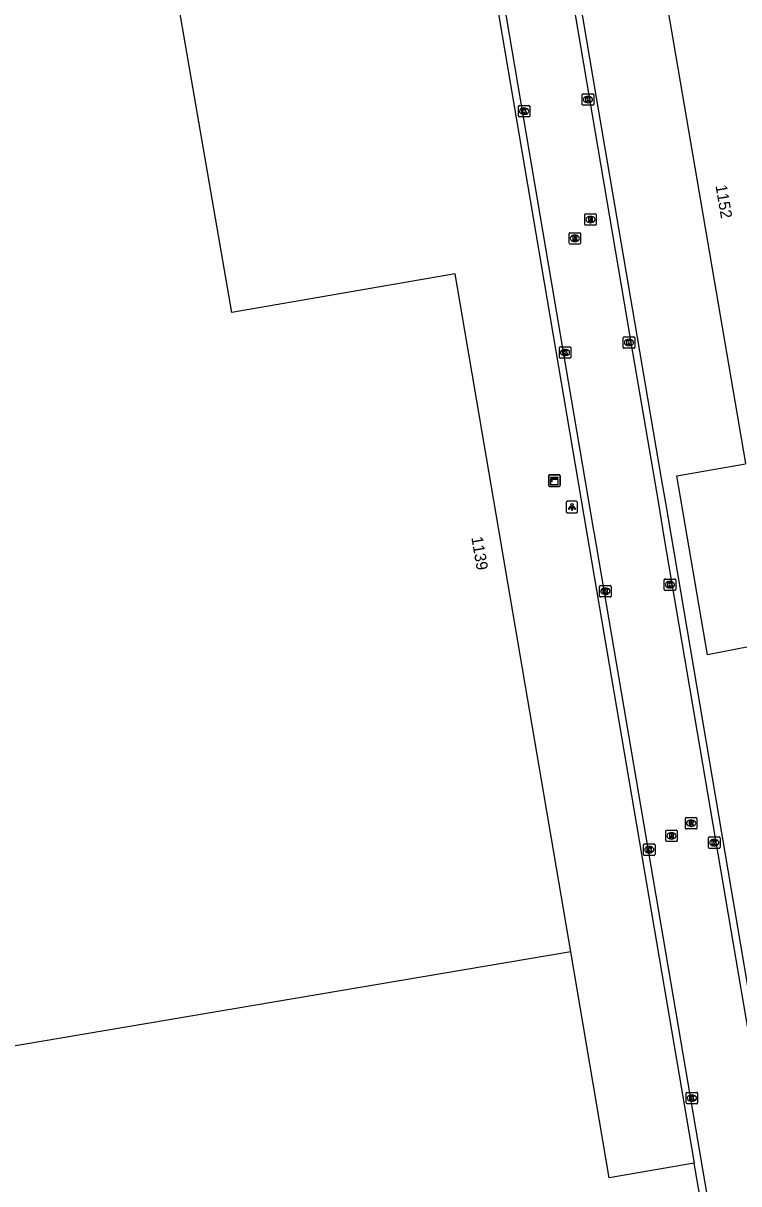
# Model space of a CAD drawing. Extents: x 154324 to 155743, y 382939 to 384183.
# Drawn here: x 154819.6 to 154882.3, y 383668.1 to 383769.7 of the extents above; entities that cross this region are included whole.
import ezdxf

# ---------------------------------------------------------------- set-up
doc = ezdxf.new("R2010")
doc.units = 0
for name, color, linetype in [('IMGEO_Kast', 7, 'Continuous'), ('IMGEO_Kolk', 7, 'Continuous'), ('IMGEO_Lichtpunt', 7, 'Continuous'), ('IMGEO_Pand', 7, 'Continuous'), ('IMGEO_Pand_nummerreeks', 7, 'Continuous'), ('IMGEO_Parkeervlak_open', 7, 'Continuous'), ('IMGEO_Rijbaan_lokaal_gesloten', 7, 'Continuous'), ('IMGEO_Rijbaan_lokaal_open', 7, 'Continuous'), ('IMGEO_Rioolput', 7, 'Continuous'), ('IMGEO_Voetpad_open', 7, 'Continuous')]:
    doc.layers.add(name, color=color, linetype=linetype)

msp = doc.modelspace()

# ---------------------------------------------------------------- linework, layer by layer
at = {"layer": 'IMGEO_Kast'}
for p, q in [((154865.64, 383729.2), (154865.64, 383730.04)), ((154865.64, 383730.04), (154865.64, 383729.2)), ((154865.71, 383730.12), (154866.55, 383730.12)), ((154866.55, 383730.12), (154865.71, 383730.12)), ((154866.64, 383730.05), (154866.64, 383729.21)), ((154866.64, 383729.21), (154866.64, 383730.05)), ((154866.56, 383729.12), (154865.72, 383729.12)), ((154865.72, 383729.12), (154866.56, 383729.12))]:
    msp.add_line(p, q, dxfattribs=at)
for points in [[(154865.83, 383729.91), (154866.43, 383729.91), (154866.43, 383729.83), (154865.83, 383729.83), (154865.83, 383729.91)], [(154865.83, 383729.74), (154866.43, 383729.74), (154866.43, 383729.25), (154865.83, 383729.25), (154865.83, 383729.74)]]:
    msp.add_lwpolyline(points, dxfattribs=at)
msp.add_circle((154865.91, 383729.59), 0.0377, dxfattribs=at)
for centre, start, end in [((154865.71, 383730.05), 92.4484, 184.2845), ((154865.71, 383730.05), 92.4484, 184.2845), ((154866.56, 383730.05), 2.4484, 94.2845), ((154866.56, 383730.05), 2.4484, 94.2845), ((154865.71, 383729.2), 182.4484, 274.2845), ((154865.71, 383729.2), 182.4484, 274.2845), ((154866.56, 383729.2), 272.4484, 4.2845), ((154866.56, 383729.2), 272.4484, 4.2845)]:
    msp.add_arc(centre, 0.0779, start, end, dxfattribs=at)
at = {"layer": 'IMGEO_Kolk'}
for p, q in [((154868.58, 383762.55), (154868.58, 383763.4)), ((154868.65, 383763.48), (154869.5, 383763.48)), ((154869.06, 383763.25), (154869.09, 383763.25)), ((154869.58, 383763.4), (154869.58, 383762.55)), ((154862.98, 383761.52), (154862.98, 383762.38)), ((154863.06, 383762.45), (154863.91, 383762.45)), ((154863.47, 383762.23), (154863.5, 383762.23)), ((154863.99, 383762.38), (154863.99, 383761.52)), ((154869.5, 383762.47), (154868.65, 383762.47)), ((154869.09, 383762.7), (154869.06, 383762.7)), ((154863.91, 383761.45), (154863.06, 383761.45)), ((154863.49, 383761.67), (154863.47, 383761.67)), ((154872.16, 383741.28), (154872.16, 383742.13)), ((154872.24, 383742.21), (154873.09, 383742.21)), ((154872.65, 383741.99), (154872.68, 383741.99)), ((154873.17, 383742.13), (154873.17, 383741.28)), ((154866.57, 383740.4), (154866.57, 383741.26)), ((154866.64, 383741.33), (154867.5, 383741.33)), ((154867.06, 383741.11), (154867.08, 383741.11)), ((154867.57, 383741.26), (154867.57, 383740.4)), ((154873.09, 383741.21), (154872.24, 383741.21)), ((154872.67, 383741.43), (154872.65, 383741.43)), ((154867.5, 383740.33), (154866.64, 383740.33)), ((154867.08, 383740.55), (154867.06, 383740.55)), ((154875.76, 383720.09), (154875.76, 383720.94)), ((154875.83, 383721.01), (154876.68, 383721.01)), ((154876.24, 383720.79), (154876.27, 383720.79)), ((154876.76, 383720.94), (154876.76, 383720.09)), ((154870.1, 383719.51), (154870.1, 383720.36)), ((154870.17, 383720.44), (154871.03, 383720.44)), ((154870.61, 383719.66), (154870.58, 383719.66)), ((154870.59, 383720.22), (154870.61, 383720.22)), ((154871.1, 383720.36), (154871.1, 383719.51)), ((154876.68, 383720.01), (154875.83, 383720.01)), ((154876.27, 383720.23), (154876.24, 383720.23)), ((154871.03, 383719.44), (154870.17, 383719.44)), ((154879.64, 383697.52), (154879.64, 383698.37)), ((154879.71, 383698.45), (154880.56, 383698.45)), ((154880.12, 383698.22), (154880.15, 383698.22)), ((154880.64, 383698.37), (154880.64, 383697.52)), ((154873.95, 383696.89), (154873.95, 383697.74)), ((154874.02, 383697.82), (154874.87, 383697.82)), ((154874.43, 383697.6), (154874.46, 383697.6)), ((154874.95, 383697.74), (154874.95, 383696.89)), ((154880.56, 383697.44), (154879.71, 383697.44)), ((154880.15, 383697.67), (154880.12, 383697.67)), ((154874.87, 383696.82), (154874.02, 383696.82)), ((154874.46, 383697.04), (154874.43, 383697.04)), ((154877.68, 383675.16), (154877.68, 383676.01)), ((154877.75, 383676.08), (154878.6, 383676.08)), ((154878.16, 383675.86), (154878.19, 383675.86)), ((154878.68, 383676.01), (154878.68, 383675.16)), ((154878.6, 383675.08), (154877.75, 383675.08)), ((154878.19, 383675.3), (154878.16, 383675.3))]:
    msp.add_line(p, q, dxfattribs=at)
for points in [[(154868.58, 383762.55), (154868.58, 383763.4)], [(154868.65, 383763.48), (154869.5, 383763.48)], [(154868.9, 383763.17), (154869.02, 383763.17), (154869.02, 383763.02), (154869.15, 383763.17), (154869.31, 383763.17), (154869.17, 383763.02), (154869.32, 383762.77), (154869.17, 383762.77), (154869.08, 383762.94), (154869.02, 383762.87), (154869.02, 383762.77), (154868.9, 383762.77), (154868.9, 383763.17)], [(154869.58, 383763.4), (154869.58, 383762.55)], [(154862.98, 383761.52), (154862.98, 383762.38)], [(154863.06, 383762.45), (154863.91, 383762.45)], [(154863.3, 383762.15), (154863.43, 383762.15), (154863.43, 383762), (154863.56, 383762.15), (154863.72, 383762.15), (154863.58, 383762), (154863.73, 383761.75), (154863.58, 383761.75), (154863.49, 383761.91), (154863.43, 383761.85), (154863.43, 383761.75), (154863.3, 383761.75), (154863.3, 383762.15)], [(154863.99, 383762.38), (154863.99, 383761.52)], [(154869.5, 383762.47), (154868.65, 383762.47)], [(154863.91, 383761.45), (154863.06, 383761.45)], [(154872.16, 383741.28), (154872.16, 383742.13)], [(154872.24, 383742.21), (154873.09, 383742.21)], [(154872.48, 383741.91), (154872.61, 383741.91), (154872.61, 383741.76), (154872.74, 383741.91), (154872.9, 383741.91), (154872.76, 383741.76), (154872.91, 383741.51), (154872.76, 383741.51), (154872.67, 383741.67), (154872.61, 383741.6), (154872.61, 383741.51), (154872.48, 383741.51), (154872.48, 383741.91)], [(154873.17, 383742.13), (154873.17, 383741.28)], [(154866.57, 383740.4), (154866.57, 383741.26)], [(154866.64, 383741.33), (154867.5, 383741.33)], [(154866.89, 383741.03), (154867.01, 383741.03), (154867.01, 383740.88), (154867.14, 383741.03), (154867.31, 383741.03), (154867.16, 383740.88), (154867.31, 383740.63), (154867.16, 383740.63), (154867.08, 383740.8), (154867.01, 383740.73), (154867.01, 383740.63), (154866.89, 383740.63), (154866.89, 383741.03)], [(154867.57, 383741.26), (154867.57, 383740.4)], [(154873.09, 383741.21), (154872.24, 383741.21)], [(154867.5, 383740.33), (154866.64, 383740.33)], [(154875.76, 383720.09), (154875.76, 383720.94)], [(154875.83, 383721.01), (154876.68, 383721.01)], [(154876.08, 383720.71), (154876.2, 383720.71), (154876.2, 383720.56), (154876.33, 383720.71), (154876.49, 383720.71), (154876.35, 383720.56), (154876.5, 383720.31), (154876.35, 383720.31), (154876.26, 383720.48), (154876.2, 383720.41), (154876.2, 383720.31), (154876.08, 383720.31), (154876.08, 383720.71)], [(154876.76, 383720.94), (154876.76, 383720.09)], [(154870.1, 383719.51), (154870.1, 383720.36)], [(154870.17, 383720.44), (154871.03, 383720.44)], [(154870.42, 383720.14), (154870.54, 383720.14), (154870.54, 383719.99), (154870.67, 383720.14), (154870.84, 383720.14), (154870.69, 383719.99), (154870.84, 383719.74), (154870.69, 383719.74), (154870.61, 383719.9), (154870.54, 383719.84), (154870.54, 383719.74), (154870.42, 383719.74), (154870.42, 383720.14)], [(154871.1, 383720.36), (154871.1, 383719.51)], [(154876.68, 383720.01), (154875.83, 383720.01)], [(154871.03, 383719.44), (154870.17, 383719.44)], [(154879.64, 383697.52), (154879.64, 383698.37)], [(154879.71, 383698.45), (154880.56, 383698.45)], [(154879.96, 383698.14), (154880.08, 383698.14), (154880.08, 383697.99), (154880.21, 383698.14), (154880.37, 383698.14), (154880.23, 383697.99), (154880.38, 383697.74), (154880.23, 383697.74), (154880.14, 383697.91), (154880.08, 383697.84), (154880.08, 383697.74), (154879.96, 383697.74), (154879.96, 383698.14)], [(154880.64, 383698.37), (154880.64, 383697.52)], [(154873.95, 383696.89), (154873.95, 383697.74)], [(154874.02, 383697.82), (154874.87, 383697.82)], [(154874.27, 383697.52), (154874.39, 383697.52), (154874.39, 383697.37), (154874.52, 383697.52), (154874.68, 383697.52), (154874.54, 383697.37), (154874.69, 383697.12), (154874.54, 383697.12), (154874.45, 383697.28), (154874.39, 383697.22), (154874.39, 383697.12), (154874.27, 383697.12), (154874.27, 383697.52)], [(154874.95, 383697.74), (154874.95, 383696.89)], [(154880.56, 383697.44), (154879.71, 383697.44)], [(154874.87, 383696.82), (154874.02, 383696.82)], [(154877.68, 383675.16), (154877.68, 383676.01)], [(154877.75, 383676.08), (154878.6, 383676.08)], [(154878, 383675.78), (154878.12, 383675.78), (154878.12, 383675.63), (154878.25, 383675.78), (154878.41, 383675.78), (154878.27, 383675.63), (154878.42, 383675.38), (154878.27, 383675.38), (154878.18, 383675.55), (154878.12, 383675.48), (154878.12, 383675.38), (154878, 383675.38), (154878, 383675.78)], [(154878.68, 383676.01), (154878.68, 383675.16)], [(154878.6, 383675.08), (154877.75, 383675.08)]]:
    msp.add_lwpolyline(points, dxfattribs=at)
for centre, start, end in [((154868.65, 383763.4), 91.552, 178.448), ((154868.65, 383763.4), 91.552, 178.448), ((154869.5, 383763.4), 1.552, 88.448), ((154869.5, 383763.4), 1.552, 88.448), ((154863.06, 383762.37), 91.552, 178.448), ((154863.06, 383762.37), 91.552, 178.448), ((154863.91, 383762.37), 1.552, 88.448), ((154863.91, 383762.37), 1.552, 88.448), ((154868.65, 383762.55), 181.552, 268.448), ((154868.65, 383762.55), 181.552, 268.448), ((154869.5, 383762.55), 271.552, 358.448), ((154869.5, 383762.55), 271.552, 358.448), ((154863.06, 383761.53), 181.552, 268.448), ((154863.06, 383761.53), 181.552, 268.448), ((154863.91, 383761.53), 271.552, 358.448), ((154863.91, 383761.53), 271.552, 358.448), ((154872.24, 383742.13), 91.552, 178.448), ((154872.24, 383742.13), 91.552, 178.448), ((154873.09, 383742.13), 1.552, 88.448), ((154873.09, 383742.13), 1.552, 88.448), ((154866.65, 383741.26), 91.552, 178.448), ((154866.65, 383741.26), 91.552, 178.448), ((154867.49, 383741.26), 1.552, 88.448), ((154867.49, 383741.26), 1.552, 88.448), ((154872.24, 383741.28), 181.552, 268.448), ((154872.24, 383741.28), 181.552, 268.448), ((154873.09, 383741.28), 271.552, 358.448), ((154873.09, 383741.28), 271.552, 358.448), ((154866.65, 383740.41), 181.552, 268.448), ((154866.65, 383740.41), 181.552, 268.448), ((154867.49, 383740.41), 271.552, 358.448), ((154867.49, 383740.41), 271.552, 358.448), ((154875.83, 383720.94), 91.552, 178.448), ((154875.83, 383720.94), 91.552, 178.448), ((154876.68, 383720.94), 1.552, 88.448), ((154876.68, 383720.94), 1.552, 88.448), ((154870.17, 383720.36), 91.552, 178.448), ((154870.17, 383720.36), 91.552, 178.448), ((154870.17, 383719.51), 181.552, 268.448), ((154870.17, 383719.51), 181.552, 268.448), ((154871.02, 383720.36), 1.552, 88.448), ((154871.02, 383720.36), 1.552, 88.448), ((154871.02, 383719.51), 271.552, 358.448), ((154871.02, 383719.51), 271.552, 358.448), ((154875.83, 383720.09), 181.552, 268.448), ((154875.83, 383720.09), 181.552, 268.448), ((154876.68, 383720.09), 271.552, 358.448), ((154876.68, 383720.09), 271.552, 358.448), ((154879.71, 383698.37), 91.552, 178.448), ((154879.71, 383698.37), 91.552, 178.448), ((154880.56, 383698.37), 1.552, 88.448), ((154880.56, 383698.37), 1.552, 88.448), ((154874.02, 383697.74), 91.552, 178.448), ((154874.02, 383697.74), 91.552, 178.448), ((154874.87, 383697.74), 1.552, 88.448), ((154874.87, 383697.74), 1.552, 88.448), ((154879.71, 383697.52), 181.552, 268.448), ((154879.71, 383697.52), 181.552, 268.448), ((154880.56, 383697.52), 271.552, 358.448), ((154880.56, 383697.52), 271.552, 358.448), ((154874.02, 383696.89), 181.552, 268.448), ((154874.02, 383696.89), 181.552, 268.448), ((154874.87, 383696.89), 271.552, 358.448), ((154874.87, 383696.89), 271.552, 358.448), ((154877.75, 383676.01), 91.552, 178.448), ((154877.75, 383676.01), 91.552, 178.448), ((154878.6, 383676.01), 1.552, 88.448), ((154878.6, 383676.01), 1.552, 88.448), ((154877.75, 383675.16), 181.552, 268.448), ((154877.75, 383675.16), 181.552, 268.448), ((154878.6, 383675.16), 271.552, 358.448), ((154878.6, 383675.16), 271.552, 358.448)]:
    msp.add_arc(centre, 0.0765, start, end, dxfattribs=at)
for centre, major_axis, ratio, start_param, end_param in [((154869.06, 383762.97), (-0.387, 0.002), 0.722429, 4.712389, 7.853982), ((154869.09, 383762.97), (-0.39, 0.002), 0.717154, 1.570796, 4.712389), ((154863.47, 383761.95), (-0.387, 0.002), 0.722429, 4.712389, 7.853982), ((154863.5, 383761.95), (-0.39, 0.002), 0.717154, 1.570796, 4.712389), ((154872.65, 383741.71), (-0.387, 0.002), 0.722429, 4.712389, 7.853982), ((154872.68, 383741.71), (-0.39, 0.002), 0.717154, 1.570796, 4.712389), ((154867.06, 383740.83), (-0.387, 0.002), 0.722429, 4.712389, 7.853982), ((154867.08, 383740.83), (-0.39, 0.002), 0.717154, 1.570796, 4.712389), ((154876.24, 383720.51), (-0.387, 0.002), 0.722429, 4.712389, 7.853982), ((154876.27, 383720.51), (-0.39, 0.002), 0.717154, 1.570796, 4.712389), ((154870.59, 383719.94), (-0.387, 0.002), 0.722429, 4.712389, 7.853982), ((154870.61, 383719.94), (-0.39, 0.002), 0.717154, 1.570796, 4.712389), ((154880.12, 383697.94), (-0.387, 0.002), 0.722429, 4.712389, 7.853982), ((154880.15, 383697.94), (-0.39, 0.002), 0.717154, 1.570796, 4.712389), ((154874.43, 383697.32), (-0.387, 0.002), 0.722429, 4.712389, 7.853982), ((154874.46, 383697.32), (-0.39, 0.002), 0.717154, 1.570796, 4.712389), ((154878.16, 383675.58), (-0.387, 0.002), 0.722429, 4.712389, 7.853982), ((154878.19, 383675.58), (-0.39, 0.002), 0.717154, 1.570796, 4.712389)]:
    msp.add_ellipse(centre, major_axis=major_axis, ratio=ratio, start_param=start_param, end_param=end_param, dxfattribs=at)
at = {"layer": 'IMGEO_Lichtpunt'}
for p, q in [((154867.17, 383727.71), (154867.17, 383726.91)), ((154867.17, 383727.71), (154867.17, 383726.91)), ((154868.07, 383727.81), (154867.26, 383727.81)), ((154868.07, 383727.81), (154867.26, 383727.81)), ((154868.17, 383726.91), (154868.17, 383727.71)), ((154868.17, 383726.91), (154868.17, 383727.71)), ((154867.26, 383726.81), (154868.07, 383726.81)), ((154867.26, 383726.81), (154868.07, 383726.81))]:
    msp.add_line(p, q, dxfattribs=at)
for points in [[(154867.54, 383727.38), (154867.58, 383727.35), (154867.4, 383727.09), (154867.36, 383727.12), (154867.54, 383727.38)], [(154867.65, 383727.33), (154867.69, 383727.33), (154867.69, 383727.01), (154867.65, 383727.01), (154867.65, 383727.33)], [(154867.76, 383727.35), (154867.79, 383727.38), (154867.98, 383727.11), (154867.94, 383727.09), (154867.76, 383727.35)]]:
    msp.add_lwpolyline(points, dxfattribs=at)
msp.add_circle((154867.67, 383727.51), 0.0994, dxfattribs=at)
for centre, start, end in [((154867.26, 383727.71), 90, 180), ((154867.26, 383727.71), 90, 180), ((154868.07, 383727.71), 0, 90), ((154868.07, 383727.71), 0, 90), ((154867.26, 383726.91), 180, 270), ((154867.26, 383726.91), 180, 270), ((154868.07, 383726.91), 270, 0), ((154868.07, 383726.91), 270, 360)]:
    msp.add_arc(centre, 0.0946, start, end, dxfattribs=at)
at = {"layer": 'IMGEO_Pand'}
for points in [[(154867.57, 383688.39), (154857.46, 383747.73), (154837.88, 383744.34), (154832.77, 383773.85), (154852.43, 383777.26), (154848.68, 383799.11), (154846.65, 383810.94)], [(154875.11, 383776.48), (154882.87, 383731.11)], [(154867.57, 383688.39), (154787.88, 383674.89)]]:
    msp.add_lwpolyline(points, dxfattribs=at)
at = {"layer": 'IMGEO_Parkeervlak_open'}
msp.add_lwpolyline([(154878.39, 383669.9), (154870.94, 383668.6), (154867.57, 383688.39)], dxfattribs=at)
at = {"layer": 'IMGEO_Rijbaan_lokaal_gesloten'}
for points in [[(154859.21, 383821.78), (154860.59, 383813.67), (154872.99, 383740.87), (154875.26, 383727.61), (154875.73, 383724.69), (154937.89, 383359.92)], [(154854.43, 383814.31), (154854.65, 383812.99), (154854.81, 383812.02), (154858.48, 383790.5), (154869.56, 383725.26), (154869.6, 383725.13), (154932.04, 383358.96)]]:
    msp.add_lwpolyline(points, dxfattribs=at)
at = {"layer": 'IMGEO_Rijbaan_lokaal_open'}
for points in [[(154853.94, 383813.59), (154856.18, 383800.4), (154857.87, 383790.41), (154868.95, 383725.16), (154878.39, 383669.9)], [(154867.75, 383775.23), (154869.8, 383763.15), (154873.59, 383740.95), (154875.5, 383729.82), (154875.86, 383727.69), (154876.35, 383724.76), (154883, 383685.74), (154886, 383668.1)], [(154880.3, 383658.76), (154878.39, 383669.9)]]:
    msp.add_lwpolyline(points, dxfattribs=at)
at = {"layer": 'IMGEO_Rioolput'}
for p, q in [((154868.87, 383752.97), (154869.72, 383752.97)), ((154868.8, 383752.05), (154868.8, 383752.9)), ((154869.72, 383751.97), (154868.87, 383751.97)), ((154869.28, 383752.75), (154869.31, 383752.75)), ((154869.31, 383752.19), (154869.28, 383752.19)), ((154869.8, 383752.9), (154869.8, 383752.05)), ((154867.43, 383750.39), (154867.43, 383751.24)), ((154867.5, 383751.32), (154868.35, 383751.32)), ((154867.91, 383751.1), (154867.94, 383751.1)), ((154868.43, 383751.24), (154868.43, 383750.39)), ((154868.35, 383750.32), (154867.5, 383750.32)), ((154867.94, 383750.54), (154867.91, 383750.54)), ((154877.61, 383699.21), (154877.61, 383700.06)), ((154877.68, 383700.14), (154878.53, 383700.14)), ((154878.12, 383699.36), (154878.09, 383699.36)), ((154878.1, 383699.92), (154878.12, 383699.92)), ((154878.61, 383700.06), (154878.61, 383699.21)), ((154875.89, 383698.11), (154875.89, 383698.96)), ((154875.97, 383699.03), (154876.82, 383699.03)), ((154876.38, 383698.81), (154876.4, 383698.81)), ((154876.4, 383698.25), (154876.38, 383698.25)), ((154876.89, 383698.96), (154876.89, 383698.11)), ((154878.53, 383699.14), (154877.68, 383699.14)), ((154876.82, 383698.03), (154875.97, 383698.03))]:
    msp.add_line(p, q, dxfattribs=at)
for points in [[(154868.87, 383752.97), (154869.72, 383752.97)], [(154868.8, 383752.05), (154868.8, 383752.9)], [(154869.72, 383751.97), (154868.87, 383751.97)], [(154869.38, 383752.67), (154869.13, 383752.67), (154869.13, 383752.27)], [(154869.13, 383752.27), (154869.26, 383752.27), (154869.26, 383752.44), (154869.27, 383752.44)], [(154869.31, 383752.59), (154869.26, 383752.59), (154869.26, 383752.51)], [(154869.26, 383752.51), (154869.31, 383752.51)], [(154869.31, 383752.41), (154869.39, 383752.27), (154869.52, 383752.27), (154869.46, 383752.4)], [(154869.8, 383752.9), (154869.8, 383752.05)], [(154867.43, 383750.39), (154867.43, 383751.24)], [(154867.5, 383751.32), (154868.35, 383751.32)], [(154868.02, 383751.02), (154867.76, 383751.02), (154867.76, 383750.62)], [(154868.43, 383751.24), (154868.43, 383750.39)], [(154868.35, 383750.32), (154867.5, 383750.32)], [(154867.76, 383750.62), (154867.89, 383750.62), (154867.89, 383750.78), (154867.9, 383750.78)], [(154867.94, 383750.94), (154867.89, 383750.94), (154867.89, 383750.86)], [(154867.89, 383750.86), (154867.94, 383750.86)], [(154867.94, 383750.75), (154868.02, 383750.62), (154868.16, 383750.62), (154868.09, 383750.74)], [(154877.61, 383699.21), (154877.61, 383700.06)], [(154877.68, 383700.14), (154878.53, 383700.14)], [(154878.2, 383699.83), (154877.94, 383699.84), (154877.94, 383699.44)], [(154877.94, 383699.44), (154878.07, 383699.44), (154878.07, 383699.6), (154878.08, 383699.6)], [(154878.12, 383699.76), (154878.07, 383699.76), (154878.07, 383699.67)], [(154878.07, 383699.67), (154878.12, 383699.67)], [(154878.13, 383699.57), (154878.2, 383699.44), (154878.34, 383699.44), (154878.27, 383699.56)], [(154878.61, 383700.06), (154878.61, 383699.21)], [(154875.89, 383698.11), (154875.89, 383698.96)], [(154875.97, 383699.03), (154876.82, 383699.03)], [(154876.48, 383698.73), (154876.23, 383698.73), (154876.23, 383698.33)], [(154876.23, 383698.33), (154876.35, 383698.33), (154876.35, 383698.5), (154876.36, 383698.5)], [(154876.41, 383698.65), (154876.35, 383698.65), (154876.35, 383698.57)], [(154876.35, 383698.57), (154876.4, 383698.57)], [(154876.41, 383698.47), (154876.48, 383698.33), (154876.62, 383698.33), (154876.56, 383698.46)], [(154876.89, 383698.96), (154876.89, 383698.11)], [(154878.53, 383699.14), (154877.68, 383699.14)], [(154876.82, 383698.03), (154875.97, 383698.03)]]:
    msp.add_lwpolyline(points, dxfattribs=at)
for centre, radius, start, end in [((154868.87, 383752.9), 0.0765, 91.552, 178.448), ((154868.87, 383752.9), 0.0765, 91.552, 178.448), ((154869.72, 383752.9), 0.0765, 1.552, 88.448), ((154869.72, 383752.9), 0.0765, 1.552, 88.448), ((154868.87, 383752.05), 0.0765, 181.552, 268.448), ((154868.87, 383752.05), 0.0765, 181.552, 268.448), ((154869.27, 383752.38), 0.0533, 26.0293, 88.6989), ((154869.32, 383752.5), 0.0964, 77.0061, 93.1865), ((154869.29, 383752.7), 0.19, 274.7715, 282.9687), ((154869.33, 383752.55), 0.0378, 276.6634, 79.6772), ((154869.38, 383752.56), 0.109, 350.3612, 89.416), ((154869.38, 383752.56), 0.112, 277.5842, 350.9817), ((154869.37, 383752.35), 0.108, 29.5134, 73.7905), ((154869.72, 383752.05), 0.0765, 271.552, 358.448), ((154869.72, 383752.05), 0.0765, 271.552, 358.448), ((154867.5, 383751.24), 0.0765, 91.552, 178.448), ((154867.5, 383751.24), 0.0765, 91.552, 178.448), ((154868.01, 383750.91), 0.109, 350.3612, 89.416), ((154868.35, 383751.24), 0.0765, 1.552, 88.448), ((154868.35, 383751.24), 0.0765, 1.552, 88.448), ((154867.5, 383750.39), 0.0765, 181.552, 268.448), ((154867.5, 383750.39), 0.0765, 181.552, 268.448), ((154867.9, 383750.73), 0.0533, 26.0293, 88.6989), ((154867.95, 383750.84), 0.0964, 77.0061, 93.1865), ((154867.92, 383751.05), 0.19, 274.7715, 282.9687), ((154867.96, 383750.9), 0.0378, 276.6634, 79.6772), ((154868.01, 383750.91), 0.112, 277.5842, 350.9817), ((154868, 383750.69), 0.108, 29.5134, 73.7905), ((154868.35, 383750.39), 0.0765, 271.552, 358.448), ((154868.35, 383750.39), 0.0765, 271.552, 358.448), ((154877.68, 383700.06), 0.0765, 91.552, 178.448), ((154877.68, 383700.06), 0.0765, 91.552, 178.448), ((154877.68, 383699.21), 0.0765, 181.552, 268.448), ((154877.68, 383699.21), 0.0765, 181.552, 268.448), ((154878.08, 383699.55), 0.0533, 26.0293, 88.6989), ((154878.13, 383699.66), 0.0964, 77.0061, 93.1865), ((154878.1, 383699.86), 0.19, 274.7715, 282.9687), ((154878.14, 383699.72), 0.0378, 276.6634, 79.6772), ((154878.2, 383699.72), 0.109, 350.3612, 89.416), ((154878.19, 383699.72), 0.112, 277.5842, 350.9817), ((154878.18, 383699.51), 0.108, 29.5134, 73.7905), ((154878.53, 383700.06), 0.0765, 1.552, 88.448), ((154878.53, 383700.06), 0.0765, 1.552, 88.448), ((154878.53, 383699.21), 0.0765, 271.552, 358.448), ((154878.53, 383699.21), 0.0765, 271.552, 358.448), ((154875.97, 383698.96), 0.0765, 91.552, 178.448), ((154875.97, 383698.96), 0.0765, 91.552, 178.448), ((154876.36, 383698.44), 0.0533, 26.0293, 88.6989), ((154876.39, 383698.76), 0.19, 274.7715, 282.9687), ((154876.41, 383698.56), 0.0964, 77.0061, 93.1865), ((154876.43, 383698.61), 0.0378, 276.6634, 79.6772), ((154876.48, 383698.62), 0.109, 350.3612, 89.416), ((154876.48, 383698.62), 0.112, 277.5842, 350.9817), ((154876.46, 383698.41), 0.108, 29.5134, 73.7905), ((154876.82, 383698.96), 0.0765, 1.552, 88.448), ((154876.82, 383698.96), 0.0765, 1.552, 88.448), ((154875.97, 383698.11), 0.0765, 181.552, 268.448), ((154875.97, 383698.11), 0.0765, 181.552, 268.448), ((154876.82, 383698.11), 0.0765, 271.552, 358.448), ((154876.82, 383698.11), 0.0765, 271.552, 358.448)]:
    msp.add_arc(centre, radius, start, end, dxfattribs=at)
for centre, major_axis, ratio, start_param, end_param in [((154869.28, 383752.47), (-0.387, 0.002), 0.722429, 4.712389, 7.853982), ((154869.31, 383752.47), (-0.39, 0.002), 0.717154, 1.570796, 4.712389), ((154867.91, 383750.82), (-0.387, 0.002), 0.722429, 4.712389, 7.853982), ((154867.94, 383750.82), (-0.39, 0.002), 0.717154, 1.570796, 4.712389), ((154878.09, 383699.64), (-0.387, 0.002), 0.722429, 4.712389, 7.853982), ((154878.12, 383699.64), (-0.39, 0.002), 0.717154, 1.570796, 4.712389), ((154876.38, 383698.53), (-0.387, 0.002), 0.722429, 4.712389, 7.853982), ((154876.4, 383698.53), (-0.39, 0.002), 0.717154, 1.570796, 4.712389)]:
    msp.add_ellipse(centre, major_axis=major_axis, ratio=ratio, start_param=start_param, end_param=end_param, dxfattribs=at)
at = {"layer": 'IMGEO_Voetpad_open'}
msp.add_lwpolyline([(154885.53, 383715.54), (154879.55, 383714.38), (154876.86, 383730.05), (154882.88, 383731.08)], dxfattribs=at)

# ---------------------------------------------------------------- texts
at = {"layer": 'IMGEO_Pand_nummerreeks'}
for s, rotation, p in [('1152', 279.7057, (154880.24, 383755.43)), ('1139', 279.6656, (154858.86, 383724.65))]:
    msp.add_text(s, height=1, rotation=rotation, dxfattribs=at).set_placement(p)

doc.saveas('drawing.dxf')
